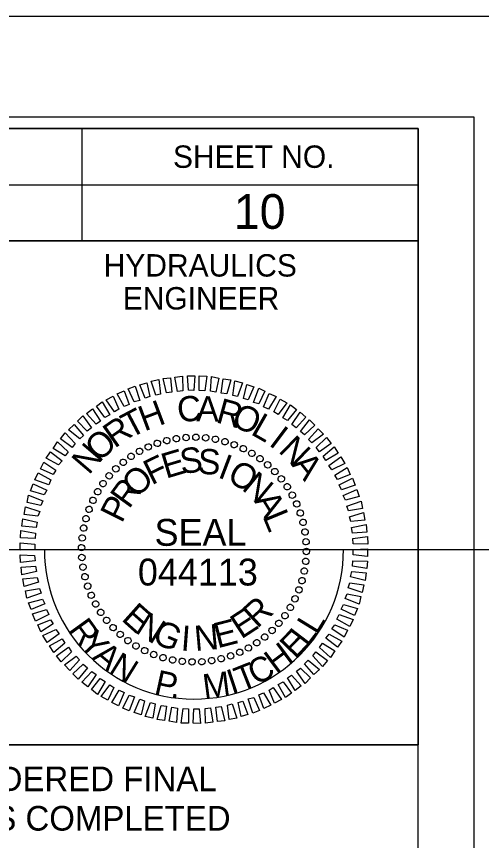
# Model space of a CAD drawing. Extents: x 1260439 to 1262228, y 742196 to 743296.
# Drawn here: x 1262016.2 to 1262119.9, y 743111.8 to 743295.7 of the extents above; entities that cross this region are included whole.
import ezdxf

# ---------------------------------------------------------------- set-up
doc = ezdxf.new("R2010")
doc.units = 0
for name, color, linetype in [('Scratch_Level_0', 7, 'Continuous'), ('Scratch_Level_1', 7, 'Continuous'), ('Sheet Cutting Line CELL', 7, 'Continuous'), ('Sheet Data Field CELL', 7, 'Continuous'), ('Sheet Plot Border Inside CELL', 7, 'Continuous'), ('Sheet Plot Border Outside CELL', 7, 'Continuous'), ('Sheet Professional Seal CELL', 7, 'Continuous'), ('Sheet Profile CELL', 7, 'Continuous'), ('Sheet Profile Grid Major CELL', 7, 'Continuous'), ('Sheet Sticker Exception Certification CELL', 7, 'Continuous')]:
    doc.layers.add(name, color=color, linetype=linetype)

msp = doc.modelspace()

# ---------------------------------------------------------------- linework, layer by layer
at = {"layer": 'Scratch_Level_0'}
msp.add_arc((1262055.75, 743176.75), 33.36, 180, 360, dxfattribs=at)
at = {"layer": 'Scratch_Level_1'}
msp.add_line((1261955.7, 743176.75), (1262228.23, 743176.75), dxfattribs=at)
at = {"layer": 'Sheet Cutting Line CELL'}
msp.add_line((1262122.75, 743295.74), (1260438.75, 743295.74), dxfattribs=at)
at = {"layer": 'Sheet Plot Border Inside CELL'}
msp.add_lwpolyline([(1260451.75, 742218.19), (1262118.25, 742218.19), (1262118.25, 743273.29), (1260451.75, 743273.29)], close=True, dxfattribs=at)
at = {"layer": 'Sheet Plot Border Outside CELL'}
msp.add_lwpolyline([(1260438.75, 742195.74), (1262122.75, 742195.74), (1262122.75, 743295.74), (1260438.75, 743295.74)], close=True, dxfattribs=at)
at = {"layer": 'Sheet Professional Seal CELL'}
for p, q in [((1262047.55, 743200.5), (1262047.55, 743200.5)), ((1262049.65, 743201.1), (1262049.65, 743201.1)), ((1262051.85, 743201.5), (1262051.85, 743201.5)), ((1262054, 743201.8), (1262054, 743201.8)), ((1262056.2, 743201.85), (1262056.2, 743201.85)), ((1262058.4, 743201.7), (1262058.4, 743201.7)), ((1262060.55, 743201.35), (1262060.55, 743201.35)), ((1262062.65, 743200.9), (1262062.65, 743200.9)), ((1262064.75, 743200.2), (1262064.75, 743200.2)), ((1262043.6, 743198.7), (1262043.6, 743198.7)), ((1262045.55, 743199.7), (1262045.55, 743199.7)), ((1262066.75, 743199.3), (1262066.75, 743199.3)), ((1262041.7, 743197.55), (1262041.7, 743197.55)), ((1262068.7, 743198.3), (1262068.7, 743198.3)), ((1262070.5, 743197.05), (1262070.5, 743197.05)), ((1262038.3, 743194.8), (1262038.3, 743194.8)), ((1262039.95, 743196.3), (1262039.95, 743196.3)), ((1262072.25, 743195.7), (1262072.25, 743195.7)), ((1262036.8, 743193.25), (1262036.8, 743193.25)), ((1262073.8, 743194.2), (1262073.8, 743194.2)), ((1262035.45, 743191.5), (1262035.45, 743191.5)), ((1262075.3, 743192.55), (1262075.3, 743192.55)), ((1262034.2, 743189.7), (1262034.2, 743189.7)), ((1262076.55, 743190.8), (1262076.55, 743190.8)), ((1262033.2, 743187.75), (1262033.2, 743187.75)), ((1262077.7, 743188.9), (1262077.7, 743188.9)), ((1262032.3, 743185.75), (1262032.3, 743185.75)), ((1262078.7, 743186.95), (1262078.7, 743186.95)), ((1262031.6, 743183.65), (1262031.6, 743183.65)), ((1262079.5, 743184.95), (1262079.5, 743184.95)), ((1262080.1, 743182.85), (1262080.1, 743182.85)), ((1262031.15, 743181.55), (1262031.15, 743181.55)), ((1262080.5, 743180.65), (1262080.5, 743180.65)), ((1262030.8, 743179.4), (1262030.8, 743179.4)), ((1262080.8, 743178.5), (1262080.8, 743178.5)), ((1262030.65, 743177.2), (1262030.65, 743177.2)), ((1262055.75, 743176.75), (1262055.75, 743176.75)), ((1262080.85, 743176.3), (1262080.85, 743176.3)), ((1262030.7, 743175), (1262030.7, 743175)), ((1262031, 743172.85), (1262031, 743172.85)), ((1262080.7, 743174.1), (1262080.7, 743174.1)), ((1262080.35, 743171.95), (1262080.35, 743171.95)), ((1262031.4, 743170.65), (1262031.4, 743170.65)), ((1262079.9, 743169.85), (1262079.9, 743169.85)), ((1262032, 743168.55), (1262032, 743168.55)), ((1262079.2, 743167.75), (1262079.2, 743167.75)), ((1262032.8, 743166.55), (1262032.8, 743166.55)), ((1262078.3, 743165.75), (1262078.3, 743165.75)), ((1262033.8, 743164.6), (1262033.8, 743164.6)), ((1262077.3, 743163.8), (1262077.3, 743163.8)), ((1262034.95, 743162.7), (1262034.95, 743162.7)), ((1262076.05, 743162), (1262076.05, 743162)), ((1262036.2, 743160.95), (1262036.2, 743160.95)), ((1262074.7, 743160.25), (1262074.7, 743160.25)), ((1262037.7, 743159.3), (1262037.7, 743159.3)), ((1262073.2, 743158.7), (1262073.2, 743158.7)), ((1262039.25, 743157.8), (1262039.25, 743157.8)), ((1262041, 743156.45), (1262041, 743156.45)), ((1262071.55, 743157.2), (1262071.55, 743157.2)), ((1262042.8, 743155.2), (1262042.8, 743155.2)), ((1262044.75, 743154.2), (1262044.75, 743154.2)), ((1262067.9, 743154.8), (1262067.9, 743154.8)), ((1262069.8, 743155.95), (1262069.8, 743155.95)), ((1262046.75, 743153.3), (1262046.75, 743153.3)), ((1262048.85, 743152.6), (1262048.85, 743152.6)), ((1262061.85, 743152.4), (1262061.85, 743152.4)), ((1262063.95, 743153), (1262063.95, 743153)), ((1262065.95, 743153.8), (1262065.95, 743153.8)), ((1262050.95, 743152.15), (1262050.95, 743152.15)), ((1262053.1, 743151.8), (1262053.1, 743151.8)), ((1262055.3, 743151.65), (1262055.3, 743151.65)), ((1262057.5, 743151.7), (1262057.5, 743151.7)), ((1262059.65, 743152), (1262059.65, 743152))]:
    msp.add_line(p, q, dxfattribs=at)
for points in [[(1262049.65, 743211.75), (1262048.85, 743214.95), (1262050.5, 743215.1), (1262050.85, 743211.9)], [(1262052.05, 743212.05), (1262051.5, 743215.25), (1262053.2, 743215.45), (1262053.25, 743212.2)], [(1262054.55, 743212.3), (1262054.3, 743215.55), (1262055.95, 743215.5), (1262055.75, 743212.25)], [(1262056.95, 743212.25), (1262056.95, 743215.5), (1262058.6, 743215.45), (1262058.15, 743212.2)], [(1262059.45, 743212.1), (1262059.65, 743215.35), (1262061.3, 743215.05), (1262060.65, 743211.9)], [(1262061.85, 743211.7), (1262062.3, 743214.9), (1262063.95, 743214.65), (1262063.05, 743211.55)], [(1262042.4, 743209.75), (1262041.1, 743212.65), (1262042.6, 743213.25), (1262043.65, 743210.05)], [(1262044.85, 743210.55), (1262043.7, 743213.55), (1262045.25, 743214), (1262045.9, 743210.9)], [(1262047.25, 743211.2), (1262046.2, 743214.35), (1262047.9, 743214.7), (1262048.3, 743211.45)], [(1262064.4, 743211.15), (1262064.9, 743214.4), (1262066.6, 743214), (1262065.45, 743210.9)], [(1262066.8, 743210.5), (1262067.55, 743213.6), (1262069.1, 743213.1), (1262067.85, 743210.15)], [(1262040.2, 743208.7), (1262038.6, 743211.5), (1262040.15, 743212.2), (1262041.3, 743209.15)], [(1262069.05, 743209.6), (1262070.2, 743212.75), (1262071.6, 743212.15), (1262070.2, 743209.25)], [(1262071.3, 743208.65), (1262072.55, 743211.6), (1262074.1, 743210.9), (1262072.4, 743208.1)], [(1262035.85, 743206.25), (1262034, 743208.8), (1262035.3, 743209.75), (1262036.95, 743206.85)], [(1262038.05, 743207.5), (1262036.2, 743210.2), (1262037.75, 743211), (1262039, 743208.1)], [(1262073.6, 743207.5), (1262074.95, 743210.35), (1262076.45, 743209.5), (1262074.55, 743206.9)], [(1262033.95, 743204.75), (1262031.8, 743207.15), (1262033.15, 743208.2), (1262034.9, 743205.4)], [(1262075.55, 743206.15), (1262077.3, 743209.05), (1262078.6, 743208), (1262076.65, 743205.55)], [(1262031.95, 743203.2), (1262029.75, 743205.4), (1262030.95, 743206.6), (1262032.9, 743203.9)], [(1262077.6, 743204.65), (1262079.45, 743207.4), (1262080.75, 743206.3), (1262078.55, 743203.95)], [(1262079.5, 743203.1), (1262081.55, 743205.7), (1262082.75, 743204.5), (1262080.45, 743202.35)], [(1262030.3, 743201.45), (1262027.75, 743203.5), (1262029, 743204.65), (1262031.1, 743202.25)], [(1262028.55, 743199.55), (1262025.95, 743201.5), (1262027.05, 743202.8), (1262029.25, 743200.45)], [(1262081.3, 743201.35), (1262083.45, 743203.7), (1262084.65, 743202.5), (1262082.05, 743200.55)], [(1262027.05, 743197.65), (1262024.35, 743199.35), (1262025.3, 743200.8), (1262027.7, 743198.6)], [(1262083.05, 743199.55), (1262085.35, 743201.8), (1262086.4, 743200.45), (1262083.75, 743198.55)], [(1262025.55, 743195.65), (1262022.75, 743197.15), (1262023.75, 743198.55), (1262026.35, 743196.55)], [(1262084.55, 743197.6), (1262087, 743199.7), (1262087.95, 743198.25), (1262085.15, 743196.65)], [(1262085.85, 743195.55), (1262088.5, 743197.45), (1262089.45, 743195.95), (1262086.55, 743194.55)], [(1262024.35, 743193.5), (1262021.5, 743194.75), (1262022.25, 743196.3), (1262024.95, 743194.45)], [(1262087.15, 743193.35), (1262089.95, 743195.1), (1262090.6, 743193.55), (1262087.75, 743192.4)], [(1262023.35, 743191.2), (1262020.25, 743192.35), (1262021, 743193.9), (1262023.85, 743192.3)], [(1262022.35, 743189), (1262019.25, 743189.9), (1262019.9, 743191.45), (1262022.9, 743190.05)], [(1262088.15, 743191.2), (1262091.1, 743192.7), (1262091.75, 743191.1), (1262088.65, 743190.1)], [(1262089.05, 743188.85), (1262092.1, 743190.15), (1262092.65, 743188.6), (1262089.55, 743187.8)], [(1262021.6, 743186.6), (1262018.5, 743187.25), (1262018.85, 743188.9), (1262022, 743187.65)], [(1262089.85, 743186.45), (1262093.05, 743187.6), (1262093.35, 743185.95), (1262090.2, 743185.4)], [(1262020.95, 743184.2), (1262017.85, 743184.6), (1262018.2, 743186.3), (1262021.35, 743185.25)], [(1262020.55, 743181.65), (1262017.35, 743181.95), (1262017.55, 743183.65), (1262020.8, 743182.85)], [(1262090.45, 743184.05), (1262093.6, 743185), (1262093.9, 743183.3), (1262090.75, 743183)], [(1262090.9, 743181.65), (1262094.15, 743182.35), (1262094.3, 743180.65), (1262091.1, 743180.45)], [(1262020.3, 743179.25), (1262017.05, 743179.35), (1262017.15, 743181), (1262020.4, 743180.45)], [(1262020.25, 743176.75), (1262017, 743176.6), (1262017, 743178.3), (1262020.25, 743177.95)], [(1262091.2, 743179.25), (1262094.45, 743179.65), (1262094.55, 743177.95), (1262091.3, 743178.05)], [(1262091.25, 743176.75), (1262094.5, 743176.9), (1262094.5, 743175.2), (1262091.25, 743175.55)], [(1262020.3, 743174.25), (1262017.05, 743173.85), (1262016.95, 743175.55), (1262020.2, 743175.45)], [(1262020.6, 743171.85), (1262017.35, 743171.15), (1262017.2, 743172.85), (1262020.4, 743173.05)], [(1262091.2, 743174.25), (1262094.45, 743174.15), (1262094.35, 743172.5), (1262091.1, 743173.05)], [(1262090.95, 743171.85), (1262094.15, 743171.55), (1262093.95, 743169.85), (1262090.7, 743170.65)], [(1262021.05, 743169.45), (1262017.9, 743168.5), (1262017.6, 743170.2), (1262020.75, 743170.5)], [(1262090.55, 743169.3), (1262093.65, 743168.9), (1262093.3, 743167.2), (1262090.15, 743168.25)], [(1262021.65, 743167.05), (1262018.45, 743165.9), (1262018.15, 743167.55), (1262021.3, 743168.1)], [(1262022.45, 743164.65), (1262019.4, 743163.35), (1262018.85, 743164.9), (1262021.95, 743165.7)], [(1262089.9, 743166.9), (1262093, 743166.25), (1262092.65, 743164.6), (1262089.5, 743165.85)], [(1262023.35, 743162.3), (1262020.4, 743160.8), (1262019.75, 743162.4), (1262022.85, 743163.4)], [(1262089.15, 743164.5), (1262092.25, 743163.6), (1262091.6, 743162.05), (1262088.6, 743163.45)], [(1262088.15, 743162.3), (1262091.25, 743161.15), (1262090.5, 743159.6), (1262087.65, 743161.2)], [(1262024.35, 743160.15), (1262021.55, 743158.4), (1262020.9, 743159.95), (1262023.75, 743161.1)], [(1262087.15, 743160), (1262090, 743158.75), (1262089.25, 743157.2), (1262086.55, 743159.05)], [(1262025.65, 743157.95), (1262023, 743156.05), (1262022.05, 743157.55), (1262024.95, 743158.95)], [(1262026.95, 743155.9), (1262024.5, 743153.8), (1262023.55, 743155.25), (1262026.35, 743156.85)], [(1262085.95, 743157.85), (1262088.75, 743156.35), (1262087.75, 743154.95), (1262085.15, 743156.95)], [(1262028.45, 743153.95), (1262026.15, 743151.7), (1262025.1, 743153.05), (1262027.75, 743154.95)], [(1262084.45, 743155.85), (1262087.15, 743154.15), (1262086.2, 743152.7), (1262083.8, 743154.9)], [(1262030.2, 743152.15), (1262028.05, 743149.8), (1262026.85, 743151), (1262029.45, 743152.95)], [(1262082.95, 743153.95), (1262085.55, 743152), (1262084.45, 743150.7), (1262082.25, 743153.05)], [(1262032, 743150.4), (1262029.95, 743147.8), (1262028.75, 743149), (1262031.05, 743151.15)], [(1262081.2, 743152.05), (1262083.75, 743150), (1262082.5, 743148.85), (1262080.4, 743151.25)], [(1262033.9, 743148.85), (1262032.05, 743146.1), (1262030.75, 743147.2), (1262032.95, 743149.55)], [(1262077.55, 743148.75), (1262079.7, 743146.35), (1262078.35, 743145.3), (1262076.6, 743148.1)], [(1262079.55, 743150.3), (1262081.75, 743148.1), (1262080.55, 743146.9), (1262078.6, 743149.6)], [(1262035.95, 743147.35), (1262034.2, 743144.45), (1262032.9, 743145.5), (1262034.85, 743147.95)], [(1262075.65, 743147.25), (1262077.5, 743144.7), (1262076.2, 743143.75), (1262074.55, 743146.65)], [(1262037.9, 743146), (1262036.55, 743143.15), (1262035.05, 743144), (1262036.95, 743146.6)], [(1262040.2, 743144.85), (1262038.95, 743141.9), (1262037.4, 743142.6), (1262039.1, 743145.4)], [(1262073.45, 743146), (1262075.3, 743143.3), (1262073.75, 743142.5), (1262072.5, 743145.4)], [(1262042.45, 743143.9), (1262041.3, 743140.75), (1262039.9, 743141.35), (1262041.3, 743144.25)], [(1262044.7, 743143), (1262043.95, 743139.9), (1262042.4, 743140.4), (1262043.65, 743143.35)], [(1262069.1, 743143.75), (1262070.4, 743140.85), (1262068.9, 743140.25), (1262067.85, 743143.45)], [(1262071.3, 743144.8), (1262072.9, 743142), (1262071.35, 743141.3), (1262070.2, 743144.35)], [(1262047.1, 743142.35), (1262046.6, 743139.1), (1262044.9, 743139.5), (1262046.05, 743142.6)], [(1262049.65, 743141.8), (1262049.2, 743138.6), (1262047.55, 743138.85), (1262048.45, 743141.95)], [(1262052.05, 743141.4), (1262051.85, 743138.15), (1262050.2, 743138.45), (1262050.85, 743141.6)], [(1262059.45, 743141.45), (1262060, 743138.25), (1262058.3, 743138.05), (1262058.25, 743141.3)], [(1262061.85, 743141.75), (1262062.65, 743138.55), (1262061, 743138.4), (1262060.65, 743141.6)], [(1262064.25, 743142.3), (1262065.3, 743139.15), (1262063.6, 743138.8), (1262063.2, 743142.05)], [(1262066.65, 743142.95), (1262067.8, 743139.95), (1262066.25, 743139.5), (1262065.6, 743142.6)], [(1262054.55, 743141.25), (1262054.55, 743138), (1262052.9, 743138.05), (1262053.35, 743141.3)], [(1262056.95, 743141.2), (1262057.2, 743137.95), (1262055.55, 743138), (1262055.75, 743141.25)]]:
    msp.add_lwpolyline(points, close=True, dxfattribs=at)
for centre, major_axis in [((1262051.83, 743201.52), (-0.113, 0.711)), ((1262054, 743201.77), (-0.05, 0.718)), ((1262056.19, 743201.83), (0.013, 0.72)), ((1262058.38, 743201.7), (0.075, 0.716)), ((1262060.54, 743201.37), (0.137, 0.707)), ((1262045.55, 743199.66), (-0.293, 0.658)), ((1262047.59, 743200.47), (-0.234, 0.681)), ((1262049.69, 743201.09), (-0.174, 0.699)), ((1262062.67, 743200.86), (0.198, 0.692)), ((1262064.74, 743200.17), (0.258, 0.672)), ((1262041.73, 743197.55), (-0.403, 0.597)), ((1262043.6, 743198.69), (-0.349, 0.63)), ((1262066.75, 743199.29), (0.316, 0.647)), ((1262068.67, 743198.25), (0.371, 0.617)), ((1262039.97, 743196.24), (-0.453, 0.56)), ((1262070.5, 743197.04), (0.423, 0.582)), ((1262038.33, 743194.79), (-0.5, 0.518)), ((1262072.21, 743195.68), (0.472, 0.543)), ((1262073.8, 743194.17), (0.518, 0.5)), ((1262036.83, 743193.21), (-0.543, 0.472)), ((1262075.24, 743192.54), (0.56, 0.453)), ((1262035.46, 743191.49), (-0.582, 0.423)), ((1262076.55, 743190.78), (0.597, 0.403)), ((1262034.26, 743189.67), (-0.617, 0.371)), ((1262077.69, 743188.91), (0.63, 0.349)), ((1262033.21, 743187.75), (-0.647, 0.316)), ((1262078.67, 743186.95), (0.658, 0.293)), ((1262032.34, 743185.74), (-0.672, 0.258)), ((1262079.47, 743184.92), (0.681, 0.234)), ((1262031.65, 743183.67), (-0.692, 0.198)), ((1262080.09, 743182.82), (0.699, 0.174)), ((1262031.13, 743181.54), (-0.707, 0.137)), ((1262030.81, 743179.37), (-0.716, 0.075)), ((1262080.53, 743180.68), (0.711, 0.113)), ((1262080.77, 743178.5), (0.718, 0.05)), ((1262030.68, 743177.19), (-0.72, 0.013)), ((1262080.83, 743176.32), (0.72, -0.013)), ((1262030.74, 743175), (-0.718, -0.05)), ((1262080.7, 743174.13), (0.716, -0.075)), ((1262030.98, 743172.83), (-0.711, -0.113)), ((1262080.37, 743171.97), (0.707, -0.137)), ((1262031.42, 743170.69), (-0.699, -0.174)), ((1262032.04, 743168.59), (-0.681, -0.234)), ((1262079.86, 743169.84), (0.692, -0.198)), ((1262032.84, 743166.55), (-0.658, -0.293)), ((1262079.17, 743167.76), (0.672, -0.258)), ((1262033.82, 743164.59), (-0.63, -0.349)), ((1262078.3, 743165.76), (0.647, -0.316)), ((1262034.96, 743162.73), (-0.597, -0.403)), ((1262077.25, 743163.84), (0.617, -0.371)), ((1262036.26, 743160.97), (-0.56, -0.453)), ((1262076.04, 743162.01), (0.582, -0.423)), ((1262037.71, 743159.33), (-0.518, -0.5)), ((1262074.68, 743160.3), (0.543, -0.472)), ((1262039.3, 743157.82), (-0.472, -0.543)), ((1262071.54, 743157.26), (0.453, -0.56)), ((1262073.18, 743158.71), (0.5, -0.518)), ((1262041.01, 743156.46), (-0.423, -0.582)), ((1262042.84, 743155.26), (-0.371, -0.617)), ((1262069.78, 743155.96), (0.403, -0.597)), ((1262044.76, 743154.21), (-0.316, -0.647)), ((1262065.96, 743153.84), (0.293, -0.658)), ((1262067.91, 743154.82), (0.349, -0.63)), ((1262046.77, 743153.34), (-0.258, -0.672)), ((1262048.84, 743152.64), (-0.198, -0.692)), ((1262050.97, 743152.13), (-0.137, -0.707)), ((1262053.13, 743151.81), (-0.075, -0.716)), ((1262055.32, 743151.68), (-0.013, -0.72)), ((1262057.5, 743151.73), (0.05, -0.718)), ((1262059.68, 743151.98), (0.113, -0.711)), ((1262061.82, 743152.42), (0.174, -0.699)), ((1262063.92, 743153.04), (0.234, -0.681))]:
    msp.add_ellipse(centre, major_axis=major_axis, ratio=0.999708, dxfattribs=at)
at = {"layer": 'Sheet Profile CELL'}
for p, q in [((1262030.75, 743270.69), (1262030.75, 743245.69)), ((1261905.7, 743258.19), (1262105.75, 743258.19))]:
    msp.add_line(p, q, dxfattribs=at)
for points in [[(1262105.75, 743270.74), (1260605.75, 743270.74), (1260605.75, 742220.74), (1262105.75, 742220.74)], [(1261905.7, 743270.74), (1262105.75, 743270.74), (1262105.75, 743245.69), (1261905.7, 743245.69)], [(1262005.75, 743245.69), (1262105.75, 743245.69), (1262105.75, 743133.19), (1262005.75, 743133.19)]]:
    msp.add_lwpolyline(points, close=True, dxfattribs=at)
at = {"layer": 'Sheet Profile Grid Major CELL'}
msp.add_lwpolyline([(1262055.75, 743109.69), (1262055.75, 742770.74), (1262105.75, 742770.74), (1262105.75, 743120.74)], dxfattribs=at)
at = {"layer": 'Sheet Sticker Exception Certification CELL'}
for p, q in [((1261905.7, 743133.19), (1262105.74, 743133.19)), ((1262105.74, 743133.17), (1262105.74, 743109.67))]:
    msp.add_line(p, q, dxfattribs=at)

# ---------------------------------------------------------------- texts
at = {"layer": 'Sheet Data Field CELL'}
msp.add_text('10', height=7.75, dxfattribs=at).set_placement((1262064.66, 743248.34))
at = {"layer": 'Sheet Professional Seal CELL'}
for s, height, rotation, p in [('H', 5.64, 20.6195, (1262044.7, 743203.1)), ('C', 5.64, 6.2199, (1262052.3, 743205.1)), ('A', 5.64, 359.0203, (1262056.25, 743205.4)), ('R', 5.64, 344.6211, (1262060.45, 743205.2)), ('T', 5.64, 27.8198, (1262041.45, 743201.45)), ('O', 5.64, 337.4212, (1262063.8, 743204.45)), ('R', 5.64, 35.0205, (1262038.05, 743199.25)), ('L', 5.64, 330.2209, (1262068.2, 743202.6)), ('I', 5.64, 323.0201, (1262072.25, 743200.2)), ('O', 5.64, 42.2217, (1262034.6, 743196.15)), ('N', 5.64, 315.8189, (1262074.4, 743198.65)), ('N', 5.64, 49.4235, (1262032.3, 743193.25)), ('E', 5.64, 16.6111, (1262049.5, 743192.55)), ('S', 5.64, 7.2556, (1262052.95, 743193.6)), ('S', 5.64, 357.9004, (1262056.55, 743193.65)), ('F', 5.64, 25.967, (1262046.3, 743191.05)), ('I', 5.64, 339.1896, (1262060.85, 743192.95)), ('A', 5.64, 308.6172, (1262077.35, 743195.7)), ('O', 5.64, 44.6812, (1262043, 743188.1)), ('O', 5.64, 329.8335, (1262062.85, 743192.25)), ('N', 5.64, 320.4766, (1262066.2, 743190.25)), ('R', 5.64, 54.0397, (1262041.25, 743185.65)), ('P', 5.64, 63.3989, (1262039.65, 743182.45)), ('A', 5.64, 301.7603, (1262069.05, 743187.65)), ('L', 5.64, 292.4008, (1262071, 743184.2)), ('SEAL', 5.998, 360, (1262046.96, 743177.6)), ('044113', 5.998, 360, (1262043.24, 743168.74)), ('R', 5.64, 42.4814, (1262069.85, 743159)), ('E', 5.64, 318.2769, (1262039.35, 743161.1)), ('E', 5.64, 33.1241, (1262066.3, 743156.65)), ('R', 5.5, 305.8361, (1262027.53, 743158.85)), ('N', 5.64, 327.634, (1262042.35, 743158.4)), ('G', 5.64, 336.9902, (1262046.15, 743156.15)), ('I', 5.64, 355.7012, (1262052.7, 743154.25)), ('N', 5.64, 5.0564, (1262056.05, 743154.1)), ('E', 5.64, 14.4118, (1262061, 743154.7)), ('L', 5.5, 58.4194, (1262083.12, 743157.56)), ('Y', 5.5, 312.7625, (1262029.89, 743155.58)), ('E', 5.5, 46.0262, (1262078.36, 743152.14)), ('L', 5.5, 52.6092, (1262081.04, 743154.89)), ('H', 5.5, 36.7814, (1262074.12, 743148.82)), ('A', 5.5, 320.0897, (1262032.8, 743152.45)), ('N', 5.5, 328.2755, (1262036.49, 743149.43)), ('C', 5.5, 27.9087, (1262069.59, 743146.33)), ('T', 5.5, 21.6119, (1262066.17, 743144.99)), ('P', 5.5, 347.6523, (1262046.65, 743144.59)), ('M', 5.5, 7.4156, (1262058.06, 743143.41)), ('I', 5.5, 18.0915, (1262064.2, 743144.41)), ('.', 5.5, 354.2353, (1262050.4, 743143.76))]:
    msp.add_text(s, height=height, rotation=rotation, dxfattribs=at).set_placement(p)
at = {"layer": 'Sheet Profile CELL'}
for s, p in [('SHEET NO.', (1262051.07, 743261.95)), ('HYDRAULICS', (1262035.61, 743237.69)), ('ENGINEER', (1262039.86, 743230.34))]:
    msp.add_text(s, height=5, dxfattribs=at).set_placement(p)
at = {"layer": 'Sheet Sticker Exception Certification CELL'}
for s, p in [('DOCUMENT NOT CONSIDERED FINAL', (1261926.78, 743122.84)), ('UNLESS ALL SIGNATURES COMPLETED', (1261921.7, 743114.04))]:
    msp.add_text(s, height=5.5, dxfattribs=at).set_placement(p)

doc.saveas('drawing.dxf')
